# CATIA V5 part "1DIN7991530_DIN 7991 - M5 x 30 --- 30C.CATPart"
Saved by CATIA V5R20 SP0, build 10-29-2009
Part number: 1DIN7991530_DIN 7991 - M5 x 30 --- 30C
Revision: ANY
Definition: UNKNOWN
Nomenclature: 1DIN7991530_DIN 7991 - M5 x 30 --- 30C
Source: Unknown
Bounding box of the stored display mesh (mm): x 0 to 30, y -4.82 to 4.82, z -4.82 to 4.82
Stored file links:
  C:\Users\Utente\Desktop\IO LAVORO\3D X SITO CF\CUMSA\3D files PO\PO 200530\1DIN7991530_DIN 7991 - M5 x 30 --- 30C.CATPart
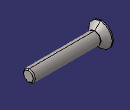
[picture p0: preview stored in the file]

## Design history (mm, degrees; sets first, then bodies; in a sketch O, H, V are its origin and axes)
Body1 "Hex" (main body)
  Solid1: solid without history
